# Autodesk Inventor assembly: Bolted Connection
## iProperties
Created: 2007-11
Part Number: Bolted Connection
Document SubType Name: Assembly
Designer: CM
Mass: 16.4955 g
Surface Area: 15.5958 cm^2
Volume: 2.12561 cm^3
Density: 7.76035 g/cm^3
ClientObjectVersion: 1
Author: CM
